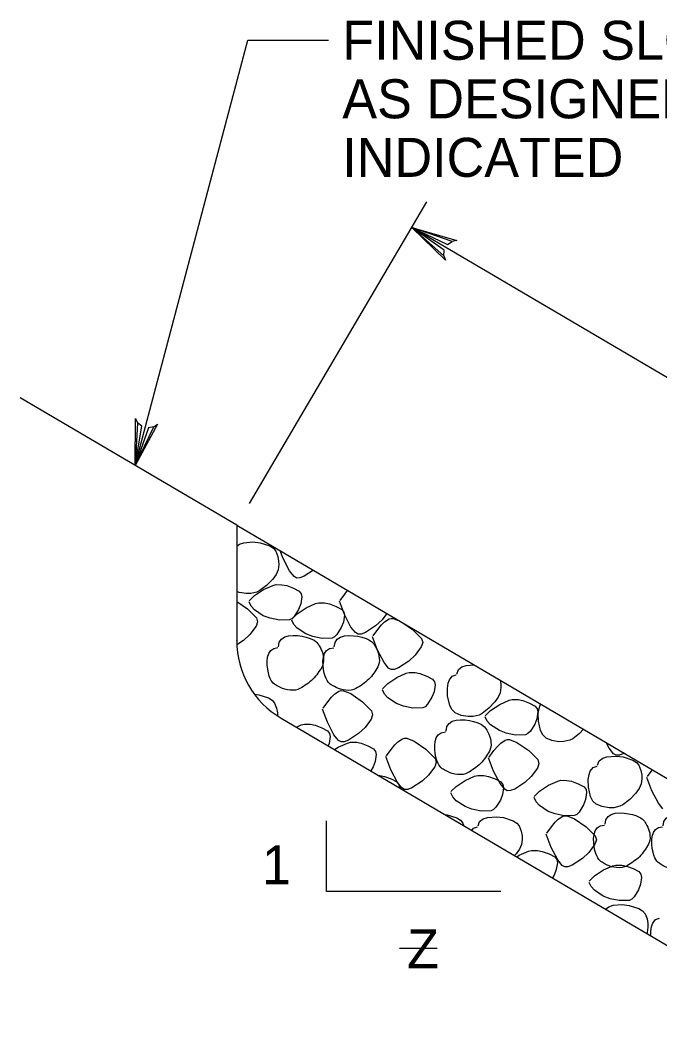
# Model space of a CAD drawing. Extents: x 636462 to 638208, y 299350 to 300538.
# Drawn here: x 637683.4 to 637732.6, y 299583.4 to 299660.9 of the extents above; entities that cross this region are included whole.
import ezdxf

# ---------------------------------------------------------------- set-up
doc = ezdxf.new("R2010")
doc.units = 0
doc.layers.add('1', color=7, linetype='Continuous')
doc.layers.add('Default', color=7, linetype='Continuous')

msp = doc.modelspace()

# ---------------------------------------------------------------- linework, layer by layer
at = {"layer": '1'}
msp.add_line((637712.574, 299589.627), (637715.466, 299589.627), dxfattribs=at)
at = {"layer": 'Default'}
for p, q in [((637701.036, 299623.788), (637714.664, 299646.955)), ((637760.498, 299617.357), (637713.512, 299644.996)), ((637700.057, 299622.12), (637683.407, 299631.913)), ((637700.057, 299620.496), (637700.276, 299620.662)), ((637700.276, 299620.662), (637700.603, 299620.773)), ((637700.603, 299620.773), (637701.296, 299620.828)), ((637701.296, 299620.828), (637701.851, 299620.764)), ((637701.851, 299620.764), (637702.595, 299620.519)), ((637702.595, 299620.519), (637702.874, 299620.34)), ((637702.874, 299620.34), (637703.058, 299620.126)), ((637703.058, 299620.126), (637703.215, 299619.72)), ((637703.215, 299619.72), (637703.277, 299619.365)), ((637703.613, 299619.559), (637703.392, 299620.158)), ((637704.115, 299618.599), (637703.613, 299619.559)), ((637703.286, 299619.091), (637703.231, 299618.691)), ((637703.277, 299619.365), (637703.286, 299619.091)), ((637702.818, 299617.981), (637702.355, 299617.495)), ((637703.079, 299618.338), (637702.818, 299617.981)), ((637703.231, 299618.691), (637703.079, 299618.338)), ((637704.468, 299618.172), (637704.115, 299618.599)), ((637704.663, 299618.057), (637704.468, 299618.172)), ((637704.907, 299618.064), (637704.663, 299618.057)), ((637705.237, 299618.189), (637704.907, 299618.064)), ((637705.946, 299618.656), (637705.237, 299618.189)), ((637702.355, 299617.495), (637701.83, 299617.088)), ((637702.118, 299617.168), (637702.837, 299617.493)), ((637702.837, 299617.493), (637703.074, 299617.553)), ((637703.074, 299617.553), (637703.532, 299617.548)), ((637703.532, 299617.548), (637703.894, 299617.472)), ((637703.894, 299617.472), (637704.412, 299617.283)), ((637704.412, 299617.283), (637704.848, 299617.046)), ((637700.23, 299616.949), (637700.057, 299617.018)), ((637700.769, 299616.86), (637700.23, 299616.949)), ((637701.137, 299616.866), (637700.769, 299616.86)), ((637701.008, 299616.309), (637701.423, 299616.708)), ((637701.6, 299616.972), (637701.137, 299616.866)), ((637701.423, 299616.708), (637702.118, 299617.168)), ((637701.83, 299617.088), (637701.6, 299616.972)), ((637704.848, 299617.046), (637705.002, 299616.85)), ((637705.05, 299616.604), (637704.974, 299616.072)), ((637705.002, 299616.85), (637705.05, 299616.604)), ((637707.994, 299616.337), (637708.355, 299616.827)), ((637708.355, 299616.827), (637708.583, 299617.104)), ((637700.057, 299616.265), (637700.872, 299615.703)), ((637700.872, 299615.703), (637701.57, 299615.01)), ((637701.169, 299615.895), (637701.008, 299616.222)), ((637701.416, 299615.611), (637701.169, 299615.895)), ((637704.815, 299615.653), (637704.481, 299615.114)), ((637704.702, 299615.305), (637705.398, 299615.766)), ((637704.974, 299616.072), (637704.815, 299615.653)), ((637705.398, 299615.766), (637706.119, 299616.09)), ((637706.119, 299616.09), (637706.354, 299616.148)), ((637706.354, 299616.148), (637706.815, 299616.143)), ((637706.815, 299616.143), (637707.174, 299616.07)), ((637707.174, 299616.07), (637707.692, 299615.881)), ((637707.692, 299615.881), (637708.127, 299615.643)), ((637708.328, 299615.25), (637707.95, 299616.27)), ((637708.127, 299615.643), (637708.284, 299615.448)), ((637702.098, 299615.164), (637701.416, 299615.611)), ((637701.57, 299615.01), (637701.653, 299614.695)), ((637702.627, 299614.962), (637702.098, 299615.164)), ((637703.337, 299614.812), (637702.627, 299614.962)), ((637704.295, 299614.932), (637704.111, 299614.835)), ((637704.288, 299614.906), (637704.702, 299615.305)), ((637704.481, 299615.114), (637704.295, 299614.932)), ((637708.33, 299615.199), (637708.254, 299614.669)), ((637708.284, 299615.448), (637708.33, 299615.199)), ((637708.83, 299614.289), (637708.328, 299615.25)), ((637711.589, 299615.337), (637711.225, 299614.847)), ((637711.419, 299614.681), (637711.764, 299614.911)), ((637711.764, 299614.911), (637711.935, 299614.957)), ((637711.935, 299614.957), (637712.103, 299614.95)), ((637712.103, 299614.95), (637712.55, 299614.771)), ((637701.547, 299614.361), (637701.073, 299613.72)), ((637701.653, 299614.695), (637701.547, 299614.361)), ((637704.111, 299614.835), (637703.337, 299614.812)), ((637704.449, 299614.492), (637704.288, 299614.817)), ((637704.698, 299614.206), (637704.449, 299614.492)), ((637705.38, 299613.762), (637704.698, 299614.206)), ((637708.095, 299614.25), (637707.761, 299613.711)), ((637708.254, 299614.669), (637708.095, 299614.25)), ((637709.185, 299613.863), (637708.83, 299614.289)), ((637710.728, 299614.391), (637709.952, 299613.879)), ((637710.541, 299613.612), (637710.9, 299614.103)), ((637711.225, 299614.847), (637710.728, 299614.391)), ((637710.9, 299614.103), (637711.193, 299614.455)), ((637711.193, 299614.455), (637711.419, 299614.681)), ((637712.895, 299614.568), (637713.572, 299614.105)), ((637713.572, 299614.105), (637714.27, 299613.409)), ((637701.073, 299613.72), (637700.577, 299613.264)), ((637705.907, 299613.559), (637705.38, 299613.762)), ((637706.616, 299613.409), (637705.907, 299613.559)), ((637707.39, 299613.432), (637706.616, 299613.409)), ((637707.575, 299613.529), (637707.39, 299613.432)), ((637707.761, 299613.711), (637707.575, 299613.529)), ((637709.378, 299613.746), (637709.185, 299613.863)), ((637709.622, 299613.753), (637709.378, 299613.746)), ((637709.952, 299613.879), (637709.622, 299613.753)), ((637710.875, 299612.523), (637710.495, 299613.543)), ((637714.27, 299613.409), (637714.351, 299613.094)), ((637700.577, 299613.264), (637700.064, 299612.926)), ((637714.245, 299612.76), (637713.773, 299612.12)), ((637714.351, 299613.094), (637714.245, 299612.76)), ((637711.377, 299611.564), (637710.875, 299612.523)), ((637713.773, 299612.12), (637713.275, 299611.663)), ((637711.73, 299611.138), (637711.377, 299611.564)), ((637711.925, 299611.021), (637711.73, 299611.138)), ((637712.167, 299611.028), (637711.925, 299611.021)), ((637712.497, 299611.152), (637712.167, 299611.028)), ((637713.275, 299611.663), (637712.497, 299611.152)), ((637716.969, 299610.685), (637717.092, 299611.021)), ((637717.092, 299611.021), (637717.359, 299611.224)), ((637717.359, 299611.224), (637717.686, 299611.334)), ((637717.686, 299611.334), (637718.31, 299611.383)), ((637711.672, 299609.95), (637712.368, 299610.413)), ((637712.368, 299610.413), (637713.088, 299610.738)), ((637713.088, 299610.738), (637713.323, 299610.795)), ((637713.323, 299610.795), (637713.782, 299610.791)), ((637713.782, 299610.791), (637714.143, 299610.717)), ((637714.143, 299610.717), (637714.662, 299610.526)), ((637714.662, 299610.526), (637715.097, 299610.291)), ((637715.097, 299610.291), (637715.251, 299610.093)), ((637716.318, 299609.98), (637716.41, 299610.233)), ((637716.41, 299610.233), (637716.619, 299610.51)), ((637716.619, 299610.51), (637716.926, 299610.618)), ((637711.257, 299609.554), (637711.672, 299609.95)), ((637711.419, 299609.139), (637711.257, 299609.464)), ((637715.3, 299609.846), (637715.224, 299609.317)), ((637715.251, 299610.093), (637715.3, 299609.846)), ((637716.253, 299609.584), (637716.318, 299609.98)), ((637716.267, 299609.006), (637716.253, 299609.584)), ((637720.311, 299610.206), (637720.36, 299609.927)), ((637720.369, 299609.65), (637720.314, 299609.25)), ((637720.36, 299609.927), (637720.369, 299609.65)), ((637701.413, 299609.132), (637701.752, 299609.093)), ((637701.752, 299609.093), (637702.496, 299608.851)), ((637702.496, 299608.851), (637702.775, 299608.669)), ((637702.775, 299608.669), (637702.959, 299608.455)), ((637707.049, 299608.552), (637707.342, 299608.907)), ((637707.342, 299608.907), (637707.568, 299609.132)), ((637707.568, 299609.132), (637707.911, 299609.36)), ((637707.911, 299609.36), (637708.084, 299609.409)), ((637708.084, 299609.409), (637708.252, 299609.402)), ((637708.252, 299609.402), (637708.816, 299609.176)), ((637708.816, 299609.176), (637709.719, 299608.556)), ((637711.665, 299608.854), (637711.419, 299609.139)), ((637712.347, 299608.407), (637711.665, 299608.854)), ((637715.065, 299608.897), (637714.731, 299608.358)), ((637715.224, 299609.317), (637715.065, 299608.897)), ((637716.437, 299608.273), (637716.267, 299609.006)), ((637720.162, 299608.9), (637719.901, 299608.543)), ((637720.314, 299609.25), (637720.162, 299608.9)), ((637720.268, 299608.34), (637720.986, 299608.665)), ((637720.986, 299608.665), (637721.223, 299608.722)), ((637721.223, 299608.722), (637721.682, 299608.718)), ((637721.682, 299608.718), (637722.041, 299608.644)), ((637702.959, 299608.455), (637703.116, 299608.052)), ((637703.116, 299608.052), (637703.18, 299607.697)), ((637707.024, 299606.974), (637706.644, 299607.994)), ((637706.688, 299608.061), (637707.049, 299608.552)), ((637709.719, 299608.556), (637710.417, 299607.861)), ((637712.877, 299608.204), (637712.347, 299608.407)), ((637713.586, 299608.057), (637712.877, 299608.204)), ((637714.36, 299608.08), (637713.586, 299608.057)), ((637714.544, 299608.174), (637714.36, 299608.08)), ((637714.731, 299608.358), (637714.544, 299608.174)), ((637716.608, 299607.941), (637716.437, 299608.273)), ((637716.859, 299607.693), (637716.608, 299607.941)), ((637719.438, 299608.054), (637718.913, 299607.649)), ((637719.901, 299608.543), (637719.438, 299608.054)), ((637719.572, 299607.877), (637720.268, 299608.34)), ((637722.041, 299608.644), (637722.562, 299608.453)), ((637722.562, 299608.453), (637722.997, 299608.218)), ((637722.997, 299608.218), (637723.151, 299608.022)), ((637723.151, 299608.022), (637723.2, 299607.773)), ((637723.227, 299607.649), (637723.292, 299608.045)), ((637723.292, 299608.045), (637723.384, 299608.298)), ((637723.384, 299608.298), (637723.437, 299608.368)), ((637703.18, 299607.697), (637703.187, 299607.462)), ((637710.394, 299607.211), (637709.919, 299606.571)), ((637710.5, 299607.545), (637710.394, 299607.211)), ((637710.417, 299607.861), (637710.5, 299607.545)), ((637717.313, 299607.508), (637716.859, 299607.693)), ((637717.852, 299607.421), (637717.313, 299607.508)), ((637718.22, 299607.428), (637717.852, 299607.421)), ((637718.683, 299607.532), (637718.22, 299607.428)), ((637718.913, 299607.649), (637718.683, 299607.532)), ((637719.155, 299607.481), (637719.572, 299607.877)), ((637719.316, 299607.066), (637719.155, 299607.391)), ((637723.121, 299607.244), (637722.965, 299606.824)), ((637723.2, 299607.773), (637723.121, 299607.244)), ((637723.241, 299607.069), (637723.227, 299607.649)), ((637704.64, 299606.599), (637705.02, 299606.769)), ((637705.02, 299606.769), (637705.255, 299606.829)), ((637705.255, 299606.829), (637705.716, 299606.824)), ((637705.716, 299606.824), (637706.075, 299606.748)), ((637706.075, 299606.748), (637706.593, 299606.56)), ((637706.593, 299606.56), (637707.029, 299606.322)), ((637707.524, 299606.014), (637707.024, 299606.974)), ((637709.919, 299606.571), (637709.424, 299606.115)), ((637719.565, 299606.781), (637719.316, 299607.066)), ((637720.247, 299606.334), (637719.565, 299606.781)), ((637722.965, 299606.824), (637722.628, 299606.285)), ((637723.412, 299606.336), (637723.241, 299607.069)), ((637723.582, 299606.004), (637723.412, 299606.336)), ((637726.717, 299606.437), (637726.413, 299606.117)), ((637707.029, 299606.322), (637707.185, 299606.127)), ((637707.231, 299605.88), (637707.155, 299605.348)), ((637707.185, 299606.127), (637707.231, 299605.88)), ((637707.879, 299605.588), (637707.524, 299606.014)), ((637708.072, 299605.472), (637707.879, 299605.588)), ((637708.646, 299605.604), (637708.316, 299605.479)), ((637709.424, 299606.115), (637708.646, 299605.604)), ((637712.448, 299605.475), (637712.791, 299605.705)), ((637712.791, 299605.705), (637712.962, 299605.753)), ((637712.962, 299605.753), (637713.132, 299605.747)), ((637713.132, 299605.747), (637713.697, 299605.518)), ((637720.777, 299606.131), (637720.247, 299606.334)), ((637720.346, 299605.378), (637720.691, 299605.608)), ((637720.691, 299605.608), (637720.862, 299605.654)), ((637721.484, 299605.984), (637720.777, 299606.131)), ((637720.862, 299605.654), (637721.03, 299605.647)), ((637721.03, 299605.647), (637721.597, 299605.422)), ((637722.26, 299606.007), (637721.484, 299605.984)), ((637722.442, 299606.104), (637722.26, 299606.007)), ((637722.628, 299606.285), (637722.442, 299606.104)), ((637723.833, 299605.756), (637723.582, 299606.004)), ((637724.287, 299605.574), (637723.833, 299605.756)), ((637724.826, 299605.484), (637724.287, 299605.574)), ((637725.657, 299605.597), (637725.194, 299605.491)), ((637725.885, 299605.712), (637725.657, 299605.597)), ((637726.413, 299606.117), (637725.885, 299605.712)), ((637707.155, 299605.348), (637707.084, 299605.159)), ((637707.57, 299604.874), (637707.846, 299605.058)), ((637707.846, 299605.058), (637708.567, 299605.383)), ((637708.316, 299605.479), (637708.072, 299605.472)), ((637708.567, 299605.383), (637708.802, 299605.442)), ((637708.802, 299605.442), (637709.263, 299605.438)), ((637709.263, 299605.438), (637709.622, 299605.362)), ((637709.622, 299605.362), (637710.14, 299605.173)), ((637710.14, 299605.173), (637710.576, 299604.936)), ((637710.576, 299604.936), (637710.732, 299604.74)), ((637711.568, 299604.406), (637711.928, 299604.897)), ((637711.928, 299604.897), (637712.22, 299605.249)), ((637712.22, 299605.249), (637712.448, 299605.475)), ((637713.697, 299605.518), (637714.599, 299604.899)), ((637714.599, 299604.899), (637715.297, 299604.206)), ((637719.468, 299604.307), (637719.828, 299604.798)), ((637719.828, 299604.798), (637720.12, 299605.152)), ((637720.12, 299605.152), (637720.346, 299605.378)), ((637721.597, 299605.422), (637722.499, 299604.802)), ((637722.499, 299604.802), (637723.197, 299604.107)), ((637725.194, 299605.491), (637724.826, 299605.484)), ((637728.677, 299604.986), (637728.451, 299605.417)), ((637729.029, 299604.56), (637728.677, 299604.986)), ((637710.778, 299604.494), (637710.702, 299603.962)), ((637710.732, 299604.74), (637710.778, 299604.494)), ((637711.902, 299603.319), (637711.525, 299604.339)), ((637715.297, 299604.206), (637715.378, 299603.89)), ((637719.802, 299603.22), (637719.422, 299604.24)), ((637723.197, 299604.107), (637723.278, 299603.791)), ((637727.917, 299604.01), (637728.186, 299604.21)), ((637728.186, 299604.21), (637728.511, 299604.321)), ((637728.511, 299604.321), (637729.204, 299604.376)), ((637729.225, 299604.443), (637729.029, 299604.56)), ((637729.204, 299604.376), (637729.759, 299604.312)), ((637729.469, 299604.45), (637729.225, 299604.443)), ((637729.798, 299604.576), (637729.469, 299604.45)), ((637729.759, 299604.312), (637730.503, 299604.067)), ((637729.838, 299604.602), (637729.798, 299604.576)), ((637730.503, 299604.067), (637730.782, 299603.888)), ((637710.543, 299603.545), (637710.355, 299603.236)), ((637710.702, 299603.962), (637710.543, 299603.545)), ((637712.404, 299602.358), (637711.902, 299603.319)), ((637715.272, 299603.556), (637714.8, 299602.916)), ((637715.378, 299603.89), (637715.272, 299603.556)), ((637723.172, 299603.457), (637722.7, 299602.817)), ((637723.278, 299603.791), (637723.172, 299603.457)), ((637727.235, 299603.222), (637727.447, 299603.499)), ((637727.447, 299603.499), (637727.751, 299603.607)), ((637727.795, 299603.674), (637727.917, 299604.01)), ((637730.782, 299603.888), (637730.966, 299603.674)), ((637730.966, 299603.674), (637731.123, 299603.268)), ((637731.123, 299603.268), (637731.185, 299602.916)), ((637731.629, 299602.805), (637731.991, 299603.296)), ((637731.991, 299603.296), (637732.012, 299603.324)), ((637710.94, 299602.893), (637711.057, 299602.891)), ((637711.057, 299602.891), (637711.416, 299602.817)), ((637711.416, 299602.817), (637711.935, 299602.628)), ((637711.935, 299602.628), (637712.372, 299602.391)), ((637714.8, 299602.916), (637714.302, 299602.46)), ((637716.928, 299602.052), (637717.624, 299602.513)), ((637717.624, 299602.513), (637718.342, 299602.838)), ((637718.342, 299602.838), (637718.579, 299602.895)), ((637718.579, 299602.895), (637719.038, 299602.891)), ((637719.038, 299602.891), (637719.397, 299602.817)), ((637719.397, 299602.817), (637719.918, 299602.628)), ((637720.305, 299602.262), (637719.802, 299603.22)), ((637719.918, 299602.628), (637720.353, 299602.391)), ((637722.7, 299602.817), (637722.202, 299602.361)), ((637724.022, 299602.137), (637724.741, 299602.462)), ((637724.741, 299602.462), (637724.978, 299602.52)), ((637724.978, 299602.52), (637725.436, 299602.515)), ((637725.436, 299602.515), (637725.795, 299602.441)), ((637727.081, 299602.573), (637727.143, 299602.969)), ((637727.092, 299601.995), (637727.081, 299602.573)), ((637727.143, 299602.969), (637727.235, 299603.222)), ((637731.196, 299602.639), (637731.141, 299602.239)), ((637731.185, 299602.916), (637731.196, 299602.639)), ((637731.966, 299601.72), (637731.586, 299602.738)), ((637712.372, 299602.391), (637712.527, 299602.195)), ((637712.757, 299601.932), (637712.404, 299602.358)), ((637712.527, 299602.195), (637712.575, 299601.948)), ((637712.575, 299601.948), (637712.573, 299601.932)), ((637712.953, 299601.815), (637712.757, 299601.932)), ((637713.197, 299601.822), (637712.953, 299601.815)), ((637713.526, 299601.948), (637713.197, 299601.822)), ((637714.302, 299602.46), (637713.526, 299601.948)), ((637716.511, 299601.654), (637716.928, 299602.052)), ((637720.657, 299601.836), (637720.305, 299602.262)), ((637720.353, 299602.391), (637720.507, 299602.195)), ((637720.556, 299601.948), (637720.48, 299601.416)), ((637720.507, 299602.195), (637720.556, 299601.948)), ((637720.853, 299601.718), (637720.657, 299601.836)), ((637721.097, 299601.725), (637720.853, 299601.718)), ((637721.424, 299601.849), (637721.097, 299601.725)), ((637722.202, 299602.361), (637721.424, 299601.849)), ((637723.326, 299601.677), (637724.022, 299602.137)), ((637725.795, 299602.441), (637726.314, 299602.253)), ((637726.314, 299602.253), (637726.751, 299602.015)), ((637726.751, 299602.015), (637726.906, 299601.82)), ((637726.906, 299601.82), (637726.954, 299601.573)), ((637727.263, 299601.262), (637727.092, 299601.995)), ((637730.989, 299601.886), (637730.727, 299601.529)), ((637731.141, 299602.239), (637730.989, 299601.886)), ((637732.466, 299600.76), (637731.966, 299601.72)), ((637716.672, 299601.239), (637716.511, 299601.564)), ((637716.921, 299600.953), (637716.672, 299601.239)), ((637717.603, 299600.509), (637716.921, 299600.953)), ((637720.321, 299600.997), (637719.984, 299600.458)), ((637720.48, 299601.416), (637720.321, 299600.997)), ((637722.909, 299601.278), (637723.326, 299601.677)), ((637723.071, 299600.864), (637722.909, 299601.188)), ((637726.876, 299601.041), (637726.719, 299600.622)), ((637726.954, 299601.573), (637726.876, 299601.041)), ((637727.433, 299600.928), (637727.263, 299601.262)), ((637727.684, 299600.682), (637727.433, 299600.928)), ((637730.264, 299601.043), (637729.739, 299600.636)), ((637730.727, 299601.529), (637730.264, 299601.043)), ((637718.133, 299600.306), (637717.603, 299600.509)), ((637718.84, 299600.157), (637718.133, 299600.306)), ((637719.616, 299600.18), (637718.84, 299600.157)), ((637719.798, 299600.276), (637719.616, 299600.18)), ((637719.984, 299600.458), (637719.798, 299600.276)), ((637723.319, 299600.578), (637723.071, 299600.864)), ((637724.001, 299600.134), (637723.319, 299600.578)), ((637726.719, 299600.622), (637726.383, 299600.083)), ((637728.138, 299600.497), (637727.684, 299600.682)), ((637728.677, 299600.408), (637728.138, 299600.497)), ((637729.048, 299600.415), (637728.677, 299600.408)), ((637729.508, 299600.52), (637729.048, 299600.415)), ((637729.739, 299600.636), (637729.508, 299600.52)), ((637732.82, 299600.334), (637732.466, 299600.76)), ((637706.953, 299593.969), (637706.953, 299599.401)), ((637716.027, 299599.901), (637716.23, 299599.876)), ((637716.23, 299599.876), (637716.974, 299599.634)), ((637716.974, 299599.634), (637717.253, 299599.452)), ((637717.253, 299599.452), (637717.437, 299599.238)), ((637718.729, 299599.348), (637718.996, 299599.549)), ((637718.996, 299599.549), (637719.321, 299599.659)), ((637719.321, 299599.659), (637720.017, 299599.714)), ((637720.017, 299599.714), (637720.572, 299599.65)), ((637720.572, 299599.65), (637721.313, 299599.406)), ((637721.313, 299599.406), (637721.594, 299599.226)), ((637724.531, 299599.931), (637724.001, 299600.134)), ((637725.238, 299599.781), (637724.531, 299599.931)), ((637724.542, 299599.295), (637724.77, 299599.523)), ((637724.77, 299599.523), (637725.114, 299599.751)), ((637725.114, 299599.751), (637725.284, 299599.8)), ((637726.014, 299599.804), (637725.238, 299599.781)), ((637725.284, 299599.8), (637725.455, 299599.793)), ((637725.455, 299599.793), (637726.019, 299599.565)), ((637726.196, 299599.901), (637726.014, 299599.804)), ((637726.019, 299599.565), (637726.922, 299598.945)), ((637726.383, 299600.083), (637726.196, 299599.901)), ((637717.437, 299599.238), (637717.52, 299599.021)), ((637718.126, 299598.664), (637718.257, 299598.837)), ((637718.257, 299598.837), (637718.561, 299598.943)), ((637718.607, 299599.01), (637718.729, 299599.348)), ((637721.594, 299599.226), (637721.776, 299599.01)), ((637721.776, 299599.01), (637721.933, 299598.607)), ((637721.933, 299598.607), (637721.997, 299598.252)), ((637723.891, 299598.452), (637724.252, 299598.943)), ((637724.252, 299598.943), (637724.542, 299599.295)), ((637726.922, 299598.945), (637727.62, 299598.252)), ((637722.007, 299597.978), (637721.951, 299597.575)), ((637721.997, 299598.252), (637722.007, 299597.978)), ((637724.225, 299597.365), (637723.847, 299598.385)), ((637727.702, 299597.936), (637727.594, 299597.602)), ((637727.62, 299598.252), (637727.702, 299597.936)), ((637721.799, 299597.225), (637721.539, 299596.868)), ((637721.769, 299596.755), (637722.488, 299597.079)), ((637721.951, 299597.575), (637721.799, 299597.225)), ((637722.488, 299597.079), (637722.725, 299597.137)), ((637722.725, 299597.137), (637723.184, 299597.132)), ((637723.184, 299597.132), (637723.543, 299597.059)), ((637723.543, 299597.059), (637724.061, 299596.87)), ((637724.727, 299596.405), (637724.225, 299597.365)), ((637727.594, 299597.602), (637727.122, 299596.962)), ((637721.539, 299596.868), (637721.41, 299596.734)), ((637721.583, 299596.63), (637721.769, 299596.755)), ((637724.061, 299596.87), (637724.499, 299596.633)), ((637724.499, 299596.633), (637724.653, 299596.437)), ((637724.653, 299596.437), (637724.701, 299596.188)), ((637725.079, 299595.979), (637724.727, 299596.405)), ((637726.625, 299596.506), (637725.848, 299595.995)), ((637727.122, 299596.962), (637726.625, 299596.506)), ((637724.623, 299595.658), (637724.466, 299595.239)), ((637724.701, 299596.188), (637724.623, 299595.658)), ((637725.275, 299595.861), (637725.079, 299595.979)), ((637725.519, 299595.868), (637725.275, 299595.861)), ((637725.848, 299595.995), (637725.519, 299595.868)), ((637727.553, 299595.168), (637728.248, 299595.628)), ((637728.248, 299595.628), (637728.967, 299595.953)), ((637728.967, 299595.953), (637729.204, 299596.011)), ((637729.204, 299596.011), (637729.663, 299596.006)), ((637729.663, 299596.006), (637730.024, 299595.932)), ((637730.024, 299595.932), (637730.542, 299595.744)), ((637730.542, 299595.744), (637730.978, 299595.506)), ((637730.978, 299595.506), (637731.132, 299595.311)), ((637724.466, 299595.239), (637724.328, 299595.018)), ((637727.136, 299594.769), (637727.553, 299595.168)), ((637731.18, 299595.064), (637731.104, 299594.532)), ((637731.132, 299595.311), (637731.18, 299595.064)), ((637720.355, 299593.969), (637706.953, 299593.969)), ((637727.299, 299594.355), (637727.136, 299594.68)), ((637727.546, 299594.069), (637727.299, 299594.355)), ((637728.228, 299593.625), (637727.546, 299594.069)), ((637730.945, 299594.113), (637730.611, 299593.574)), ((637731.104, 299594.532), (637730.945, 299594.113)), ((637728.757, 299593.422), (637728.228, 299593.625)), ((637729.464, 299593.272), (637728.757, 299593.422)), ((637730.241, 299593.295), (637729.464, 299593.272)), ((637730.425, 299593.392), (637730.241, 299593.295)), ((637730.611, 299593.574), (637730.425, 299593.392)), ((637728.407, 299592.618), (637728.658, 299592.807)), ((637728.658, 299592.807), (637728.983, 299592.918)), ((637728.983, 299592.918), (637729.679, 299592.971)), ((637729.679, 299592.971), (637730.234, 299592.908)), ((637730.234, 299592.908), (637730.978, 299592.664)), ((637730.978, 299592.664), (637731.256, 299592.482)), ((637731.256, 299592.482), (637731.441, 299592.268)), ((637731.441, 299592.268), (637731.597, 299591.865)), ((637731.597, 299591.865), (637731.659, 299591.51)), ((637732.042, 299591.54), (637732.254, 299591.817)), ((637732.254, 299591.817), (637732.558, 299591.923)), ((637731.669, 299591.234), (637731.613, 299590.833)), ((637731.659, 299591.51), (637731.669, 299591.234)), ((637731.887, 299590.891), (637731.952, 299591.287)), ((637731.894, 299590.566), (637731.887, 299590.891)), ((637731.952, 299591.287), (637732.042, 299591.54)), ((637731.613, 299590.833), (637731.579, 299590.753))]:
    msp.add_line(p, q, dxfattribs=at)
for points in [[(637692.244, 299626.716), (637700.908, 299659.372), (637707.109, 299659.372)], [(637715.98, 299642.814), (637716.099, 299642.485), (637713.512, 299644.996), (637715.98, 299642.814), (637715.998, 299643.235), (637713.512, 299644.996), (637716.257, 299643.69), (637716.604, 299643.922), (637713.512, 299644.996), (637716.976, 299643.998), (637716.604, 299643.922)], [(637693.673, 299629.684), (637693.956, 299629.888), (637692.244, 299626.716), (637693.673, 299629.684), (637693.262, 299629.587), (637692.244, 299626.716), (637692.754, 299629.713), (637692.436, 299629.984), (637692.244, 299626.716), (637692.262, 299630.321), (637692.436, 299629.984)], [(637700.057, 299622.12), (637700.057, 299613.246), (637700.056, 299613.247)], [(637700.057, 299622.12), (637747.043, 299594.481), (637785.737, 299594.481), (637832.723, 299622.12)], [(637703.462, 299607.291), (637703.461, 299607.29), (637744.03, 299583.426), (637788.747, 299583.426), (637829.316, 299607.29), (637829.315, 299607.291)]]:
    msp.add_lwpolyline(points, dxfattribs=at)
msp.add_arc((637706.965, 299613.247), 6.91, 180, 239.53444, dxfattribs=at)
for points in [[(637703.265, 299612.781), (637703.28, 299613.837), (637705.981, 299613.598), (637706.434, 299612.781), (637706.69, 299612.32), (637706.781, 299611.488), (637706.458, 299610.993), (637706.138, 299610.504), (637705.695, 299610.06), (637705.207, 299609.743), (637704.64, 299609.373), (637703.676, 299609.487), (637703.152, 299609.789), (637702.408, 299610.218), (637702.246, 299612.692), (637703.221, 299612.714)], [(637707.556, 299612.771), (637707.571, 299613.828), (637710.272, 299613.588), (637710.725, 299612.771), (637710.981, 299612.311), (637711.071, 299611.481), (637710.748, 299610.986), (637710.429, 299610.497), (637709.986, 299610.054), (637709.498, 299609.736), (637708.931, 299609.366), (637707.966, 299609.479), (637707.443, 299609.779), (637706.698, 299610.208), (637706.537, 299612.681), (637707.512, 299612.705)], [(637716.143, 299606.302), (637716.158, 299607.359), (637718.862, 299607.119), (637719.314, 299606.302), (637719.569, 299605.841), (637719.658, 299605.009), (637719.335, 299604.514), (637719.015, 299604.025), (637718.572, 299603.581), (637718.084, 299603.264), (637717.518, 299602.895), (637716.555, 299603.009), (637716.032, 299603.31), (637715.287, 299603.739), (637715.124, 299606.213), (637716.099, 299606.235)], [(637728.366, 299599.143), (637728.38, 299600.199), (637731.082, 299599.96), (637731.535, 299599.143), (637731.79, 299598.683), (637731.881, 299597.852), (637731.558, 299597.358), (637731.238, 299596.869), (637730.796, 299596.425), (637730.307, 299596.108), (637729.74, 299595.738), (637728.776, 299595.85), (637728.253, 299596.151), (637727.508, 299596.58), (637727.345, 299599.053), (637728.32, 299599.076)], [(637732.834, 299599.014), (637732.848, 299600.071), (637735.55, 299599.831), (637736.003, 299599.014), (637736.259, 299598.553), (637736.35, 299597.722), (637736.026, 299597.227), (637735.707, 299596.737), (637735.264, 299596.294), (637734.776, 299595.976), (637734.208, 299595.607), (637733.245, 299595.721), (637732.721, 299596.022), (637731.976, 299596.451), (637731.813, 299598.926), (637732.788, 299598.947)]]:
    msp.add_open_spline(points, degree=3, dxfattribs=at)

# ---------------------------------------------------------------- texts
for s, height, p in [('FINISHED SLOPE,', 2.99804, (637708.171, 299657.873)), ('AS DESIGNED OR', 2.99804, (637708.171, 299653.376)), ('INDICATED', 2.998, (637708.171, 299648.878)), ('1', 2.998, (637702, 299594.526)), ('Z', 2.998, (637713.145, 299588.068))]:
    msp.add_text(s, height=height, dxfattribs=at).set_placement(p)

doc.saveas('drawing.dxf')
